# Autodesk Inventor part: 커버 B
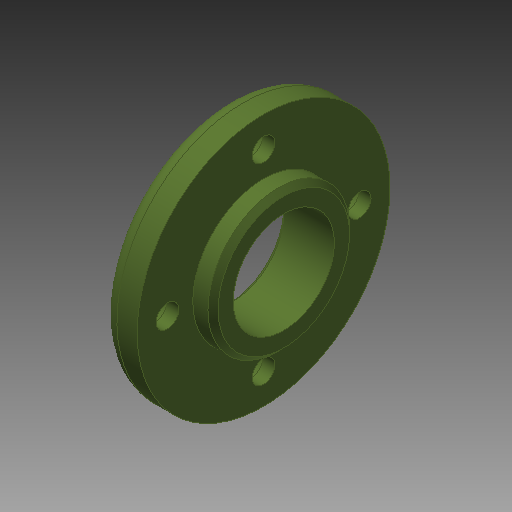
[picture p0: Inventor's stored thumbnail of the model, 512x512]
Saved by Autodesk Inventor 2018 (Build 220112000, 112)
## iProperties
Created: 2019-01
Part Number: 커버 B
Material: 알루미늄 6061
Document SubType Name: Modeling
Designer: mduedu
Density: 2.71 g/cm^3
Appearance: 올리브 녹색
Mass: 30.6342 g
Surface Area: 56.1508 cm^2
Volume: 11.3041 cm^3
Author: mduedu
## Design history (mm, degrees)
sketch "스케치1"
  geometry: L1 (0, 0)-(7, 0); L2 (7, 0)-(7, 25); L3 (7, 25)-(0, 25); L4 (0, 25)-(0, 0); L5 (7, 0)-(11, 0); L6 (11, 0)-(11, 14); L7 (11, 14)-(7, 14); L8 (7, 14)-(7, 0)
  constraints: 16 end point, 4 parallel, 2 horizontal, 2 perpendicular
  dimensions: "d0" = 50 diameter of L3 L1; "d2" = 11 distance between parallel lines of L6 L4; "d3" = 7 distance of L2.end L3.end; "d4" = 28 diameter of L7 L5
revolve "회전1" sketch "스케치1" stored, may be unused: angle "d5" = 90 deg
sketch "스케치2"
  geometry: C1 r 10 at (0, 0); 1 further point
  constraints: 1 centre point, 1 coincident
  dimensions: "d6" = 20 diameter of C1
extrude "돌출1" cut sketch "스케치2" extent not by distance; stored distance "d7" = 10; taper "d8" = 0 deg
chamfer "모따기1" distance "d9" = 1; stored, may be unused: second distance "d10" = 2, angle "d11" = 45 deg
fillet "모깎기1" dims "d12" = 3
sketch "스케치3" dims "d13" = 38
  geometry: 6 further points
  constraints: 2 vertical alignment, 1 coincident, 7 other
  dimensions: "d16" = 360 deg dimension on point (0, 0) point (0, 19) (derived)
chamfer "모따기2" distance "d18" = 1; stored, may be unused: second distance "d19" = 2, angle "d20" = 45 deg
sketch "스케치4"
  geometry: 4 further points
  constraints: 4 other
hole "구멍1" sketch "스케치4" at (-19, 0), (0, -19), (19, 0), (0, 19) diameter "d21" = 4.5; stored, may be unused: countersink angle "d25" = 90 deg, drill point angle "d27" = 0 deg; dims "d22" = 6, "d23" = 8, "d24" = 4.6, "d26" = 8
node "솔리드1"
